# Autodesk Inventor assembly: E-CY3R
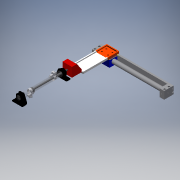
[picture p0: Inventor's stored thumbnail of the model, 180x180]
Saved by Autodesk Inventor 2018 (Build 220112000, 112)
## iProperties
Created: 2021-01
Part Number: E-CY3R
Material: Genérico
Document SubType Name: Assembly
Designer: ATOUZA
Author: ATOUZA
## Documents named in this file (6)
- D:\01 Paralaia\Grupos de Traballo\GT Maquetas\CAD 3D\E_Alimentación\E-CY3R.iam
- D:\01 Paralaia\Grupos de Traballo\GT Maquetas\CAD 3D\E_Alimentación\CY3R\SMC_JP_CY3R15200M9B000\CY3R15-200-M9B(0_0_0).iam
- D:\01 Paralaia\Grupos de Traballo\GT Maquetas\CAD 3D\E_Alimentación\SoportePieza-CY3R.ipt
- D:\01 Paralaia\Grupos de Traballo\GT Maquetas\CAD 3D\E_Alimentación\PuenteTranporte.ipt
- D:\01 Paralaia\Grupos de Traballo\GT Maquetas\CAD 3D\E_Alimentación\CD85N\SMC_JP_CD85N16100MBM9B000\CD85N16-100M-B-M9B(0__0_0).iam
- D:\01 Paralaia\Grupos de Traballo\GT Maquetas\CAD 3D\E_Alimentación\EmpujadorCilindro.ipt
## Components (5 placed, 5 different names)
1. CY3R15-200-M9B(0_0_0):1 [sub-assembly] — Insertar:1, Insertar:2
2. SoportePieza-CY3R:1 — Insertar:1, Insertar:2
3. PuenteTranporte:1 — Coincidencia:1, Coincidencia:2, Coincidencia:3
4. CD85N16-100M-B-M9B(0__0_0):1 [sub-assembly] — Ángulo:1, Coincidencia:3, Insertar:3
5. EmpujadorCilindro:1 — Ángulo:1, Coincidencia:1, Coincidencia:2, Insertar:3
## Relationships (7: Insert 3, Mate 3, Angle 1)
- Insertar:1: CY3R15-200-M9B(0_0_0):1 ↔ SoportePieza-CY3R:1
- Insertar:2: CY3R15-200-M9B(0_0_0):1 ↔ SoportePieza-CY3R:1
- Ángulo:1 [Angle]: CD85N16-100M-B-M9B(0__0_0):1 ↔ EmpujadorCilindro:1
- Coincidencia:1 [Mate]: PuenteTranporte:1 ↔ EmpujadorCilindro:1
- Coincidencia:2 [Mate]: PuenteTranporte:1 ↔ EmpujadorCilindro:1
- Coincidencia:3 [Mate]: PuenteTranporte:1 ↔ CD85N16-100M-B-M9B(0__0_0):1
- Insertar:3: CD85N16-100M-B-M9B(0__0_0):1 ↔ EmpujadorCilindro:1
